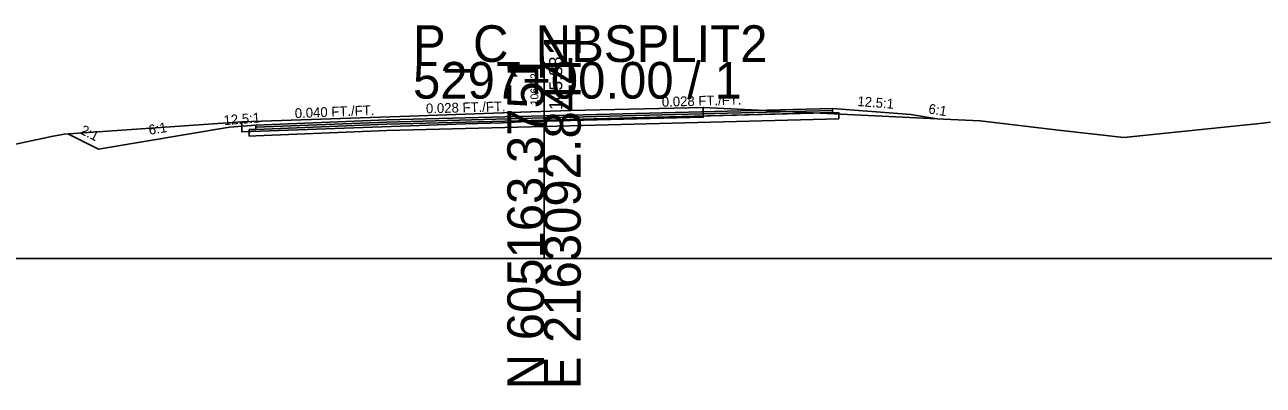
# Model space of a CAD drawing. Extents: x -26 to 1303, y -10 to 12038.
# Drawn here: x 110.4 to 204.9, y 8990.3 to 9017.8 of the extents above; entities that cross this region are included whole.
import ezdxf

# ---------------------------------------------------------------- set-up
doc = ezdxf.new("R2010")
doc.units = 0
for name, color, linetype in [('RD_GPK_XS_Cell', 7, 'Continuous'), ('RD_XS_Base', 7, 'Continuous'), ('RD_XS_ExGround', 7, 'Continuous'), ('RD_XS_ExPaveRet', 7, 'Continuous'), ('RD_XS_Greenside', 7, 'Continuous'), ('RD_XS_Pave', 7, 'Continuous'), ('RD_XS_PaveOvlay_CP', 7, 'Continuous'), ('RD_XS_TieSlope', 7, 'Continuous'), ('RD_XS_TX_Elev_EX', 7, 'Continuous'), ('RD_XS_TX_Elev_PR', 7, 'Continuous'), ('RD_XS_TX_ShdSlope', 7, 'Continuous'), ('RD_XS_TX_Slope', 7, 'Continuous')]:
    doc.layers.add(name, color=color, linetype=linetype)

msp = doc.modelspace()

# ---------------------------------------------------------------- linework, layer by layer
at = {"layer": 'RD_GPK_XS_Cell'}
for p, q in [((150, 9000), (150, 9015)), ((0, 9000), (150, 9000)), ((150, 9000), (300, 9000))]:
    msp.add_line(p, q, dxfattribs=at)
at = {"layer": 'RD_XS_Base'}
for p, q in [((150, 9010.565), (172.5, 9011.15)), ((172, 9011.137), (172, 9011.137)), ((172, 9011.137), (172, 9011.137)), ((172, 9011.137), (172, 9011.137)), ((172.5, 9011.15), (172.5, 9010.65)), ((138, 9010.253), (128, 9009.853)), ((150, 9010.565), (138, 9010.253)), ((138, 9010.253), (138, 9010.253)), ((150, 9010.065), (150, 9010.724)), ((150, 9010.724), (150, 9010.724)), ((150, 9010.724), (150, 9010.724)), ((150, 9010.724), (150, 9010.565)), ((172.5, 9010.65), (150, 9010.065)), ((150, 9010.565), (150, 9010.565)), ((150, 9010.065), (150, 9010.565)), ((150, 9010.565), (150, 9010.565)), ((150, 9010.565), (150, 9010.565)), ((172, 9010.637), (172, 9010.637)), ((172, 9010.637), (172, 9010.637)), ((172.5, 9011.117), (172.5, 9011.117)), ((128, 9009.853), (127.5, 9009.833)), ((127.5, 9009.833), (127.5, 9009.833)), ((127.5, 9009.833), (127.5, 9009.333)), ((127.5, 9009.333), (128, 9009.353)), ((128, 9009.853), (128, 9009.853)), ((128, 9009.353), (138, 9009.753)), ((128, 9009.353), (128, 9009.353)), ((138, 9009.753), (150, 9010.065)), ((138, 9009.753), (138, 9009.753)), ((150, 9010.065), (150, 9010.065))]:
    msp.add_line(p, q, dxfattribs=at)
at = {"layer": 'RD_XS_ExGround'}
msp.add_lwpolyline([(108.587, 9008.498), (112.413, 9009.311), (113.369, 9009.494), (122.562, 9010.113), (126.937, 9010.42), (139.769, 9010.859), (143.969, 9011.021), (146.865, 9011.107), (148.223, 9011.175), (152.039, 9011.281), (162.143, 9011.522), (181.042, 9010.612), (183.274, 9010.5), (189.269, 9009.779), (194.231, 9009.22), (204.843, 9010.332), (205.439, 9010.391)], dxfattribs=at)
at = {"layer": 'RD_XS_ExPaveRet'}
for points in [[(162.143, 9011.522), (162.143, 9011.522), (162.143, 9010.772), (162.143, 9010.772), (152.039, 9010.531), (152.039, 9010.531), (148.223, 9010.425), (148.223, 9010.425), (148.223, 9010.425), (148.223, 9010.425), (146.865, 9010.357), (146.865, 9010.357), (146.865, 9010.357), (143.969, 9010.271), (139.769, 9010.109), (139.769, 9010.109), (126.937, 9009.67), (126.937, 9009.67), (126.937, 9010.42), (126.937, 9010.42), (126.937, 9010.42), (139.769, 9010.859), (139.769, 9010.859), (143.969, 9011.021), (146.865, 9011.107), (146.865, 9011.107), (146.865, 9011.107), (148.223, 9011.175), (148.223, 9011.175), (148.223, 9011.175), (148.223, 9011.175), (152.039, 9011.281), (152.039, 9011.281), (162.143, 9011.522), (162.143, 9011.522)], [(162.143, 9011.522), (152.039, 9011.281), (148.223, 9011.175), (146.865, 9011.107), (143.969, 9011.021), (139.769, 9010.859), (126.937, 9010.42), (126.937, 9010.42), (126.937, 9009.67), (126.937, 9009.67), (139.769, 9010.109), (143.969, 9010.271), (146.865, 9010.357), (148.223, 9010.425), (152.039, 9010.531), (162.143, 9010.772), (162.143, 9010.772), (162.143, 9011.522), (162.143, 9011.522)]]:
    msp.add_lwpolyline(points, dxfattribs=at)
at = {"layer": 'RD_XS_Greenside'}
for p, q in [((178, 9010.975), (179.822, 9010.671)), ((116, 9008.344), (113.66, 9009.514)), ((126, 9010.011), (116, 9008.344))]:
    msp.add_line(p, q, dxfattribs=at)
at = {"layer": 'RD_XS_Pave'}
for p, q in [((172, 9011.455), (150, 9010.883)), ((172, 9011.296), (150, 9010.724)), ((150, 9010.724), (172, 9011.296)), ((150, 9010.565), (172, 9011.137)), ((172, 9011.296), (172, 9011.455)), ((172, 9011.455), (172, 9011.455)), ((172, 9011.455), (172, 9011.455)), ((172, 9011.455), (172, 9011.455)), ((172, 9011.137), (172, 9011.296)), ((172, 9011.296), (172, 9011.296)), ((172, 9011.296), (172, 9011.296)), ((172, 9011.296), (172, 9011.296)), ((172, 9011.296), (172, 9011.296)), ((172, 9011.296), (172, 9011.296)), ((172, 9011.137), (172, 9011.137)), ((172, 9011.137), (172, 9011.137)), ((138, 9010.571), (128, 9010.171)), ((128, 9010.012), (138, 9010.412)), ((138, 9010.412), (128, 9010.012)), ((128, 9009.853), (138, 9010.253)), ((150, 9010.883), (138, 9010.571)), ((138, 9010.412), (150, 9010.724)), ((150, 9010.724), (138, 9010.412)), ((138, 9010.571), (138, 9010.571)), ((138, 9010.253), (150, 9010.565)), ((138, 9010.412), (138, 9010.412)), ((138, 9010.412), (138, 9010.412)), ((138, 9010.253), (138, 9010.253)), ((150, 9010.883), (150, 9010.883)), ((150, 9010.724), (150, 9010.724)), ((150, 9010.724), (150, 9010.724)), ((150, 9010.724), (150, 9010.565)), ((150, 9010.724), (150, 9010.724)), ((150, 9010.565), (150, 9010.724)), ((150, 9010.724), (150, 9010.724)), ((150, 9010.724), (150, 9010.724)), ((150, 9010.565), (150, 9010.565)), ((150, 9010.565), (150, 9010.565)), ((128, 9010.171), (128, 9010.171)), ((128, 9010.171), (128, 9010.012)), ((128, 9010.012), (128, 9010.012)), ((128, 9010.012), (128, 9009.853))]:
    msp.add_line(p, q, dxfattribs=at)
at = {"layer": 'RD_XS_PaveOvlay_CP'}
for p, q in [((172, 9011.455), (150, 9010.883)), ((172, 9011.455), (172, 9011.455)), ((172, 9011.455), (172, 9011.455)), ((138, 9010.571), (128, 9010.171)), ((150, 9010.883), (138, 9010.571)), ((138, 9010.571), (138, 9010.571)), ((150, 9010.883), (150, 9010.883))]:
    msp.add_line(p, q, dxfattribs=at)
at = {"layer": 'RD_XS_TieSlope'}
for p, q in [((172, 9011.455), (178, 9010.975)), ((128, 9010.171), (126, 9010.011))]:
    msp.add_line(p, q, dxfattribs=at)

# ---------------------------------------------------------------- texts
at = {"layer": 'RD_GPK_XS_Cell'}
for s, p in [('P_C_NBSPLIT2', (140, 9015)), ('5297+00.00 / 1', (140, 9012.2))]:
    msp.add_text(s, height=2.8, dxfattribs=at).set_placement(p)
for s, p in [('E 2163092.8441', (152.8, 8990)), ('N 605163.3751', (150, 8990))]:
    msp.add_text(s, height=2.8, rotation=90, dxfattribs=at).set_placement(p)
at = {"layer": 'RD_XS_TX_Elev_EX'}
msp.add_text('106.22', height=0.6, rotation=90, dxfattribs=at).set_placement((149.563, 9011.683))
at = {"layer": 'RD_XS_TX_Elev_PR'}
msp.add_text('105.88', height=1, rotation=90, dxfattribs=at).set_placement((151.392, 9011.328))
at = {"layer": 'RD_XS_TX_ShdSlope'}
for rotation, p in [(355.42608, (173.893, 9011.639)), (4.57392, (125.578, 9010.167))]:
    msp.add_text('12.5:1', height=0.75, rotation=rotation, dxfattribs=at).set_placement(p)
at = {"layer": 'RD_XS_TX_Slope'}
for s, rotation, p in [('0.028 FT./FT.', 1.60386, (158.999, 9011.574)), ('0.040 FT./FT.', 2.29061, (130.995, 9010.706)), ('0.028 FT./FT.', 1.60386, (140.999, 9011.07)), ('6:1', 350.53582, (179.292, 9011.08)), ('6:1', 9.46418, (119.893, 9009.426)), ('2:1', 333.43495, (114.542, 9009.551))]:
    msp.add_text(s, height=0.75, rotation=rotation, dxfattribs=at).set_placement(p)

doc.saveas('drawing.dxf')
